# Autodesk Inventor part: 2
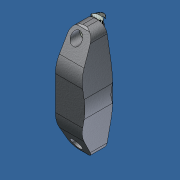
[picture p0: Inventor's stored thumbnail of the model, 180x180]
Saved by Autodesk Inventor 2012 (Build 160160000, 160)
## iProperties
Created: 2014-06
Part Number: 2
Material: Default
Document SubType Name: Modeling
Designer: Admin
Density: 1 g/cm^3
Mass: 37.1457 g
Surface Area: 173.364 cm^2
Volume: 37.1457 cm^3
Translation Standard: STEP AP214IS
FileName: 21_0959_0_1.stp
PreProcessor: ACIS
PostProcessor: Build: 160, Release: 2012 RTM - Date: Tue 03/01/2011
Sent Units: millimeter
Uncertainty: 0.0
Author: Admin
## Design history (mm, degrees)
feature "Base1"
body "Solid1"
